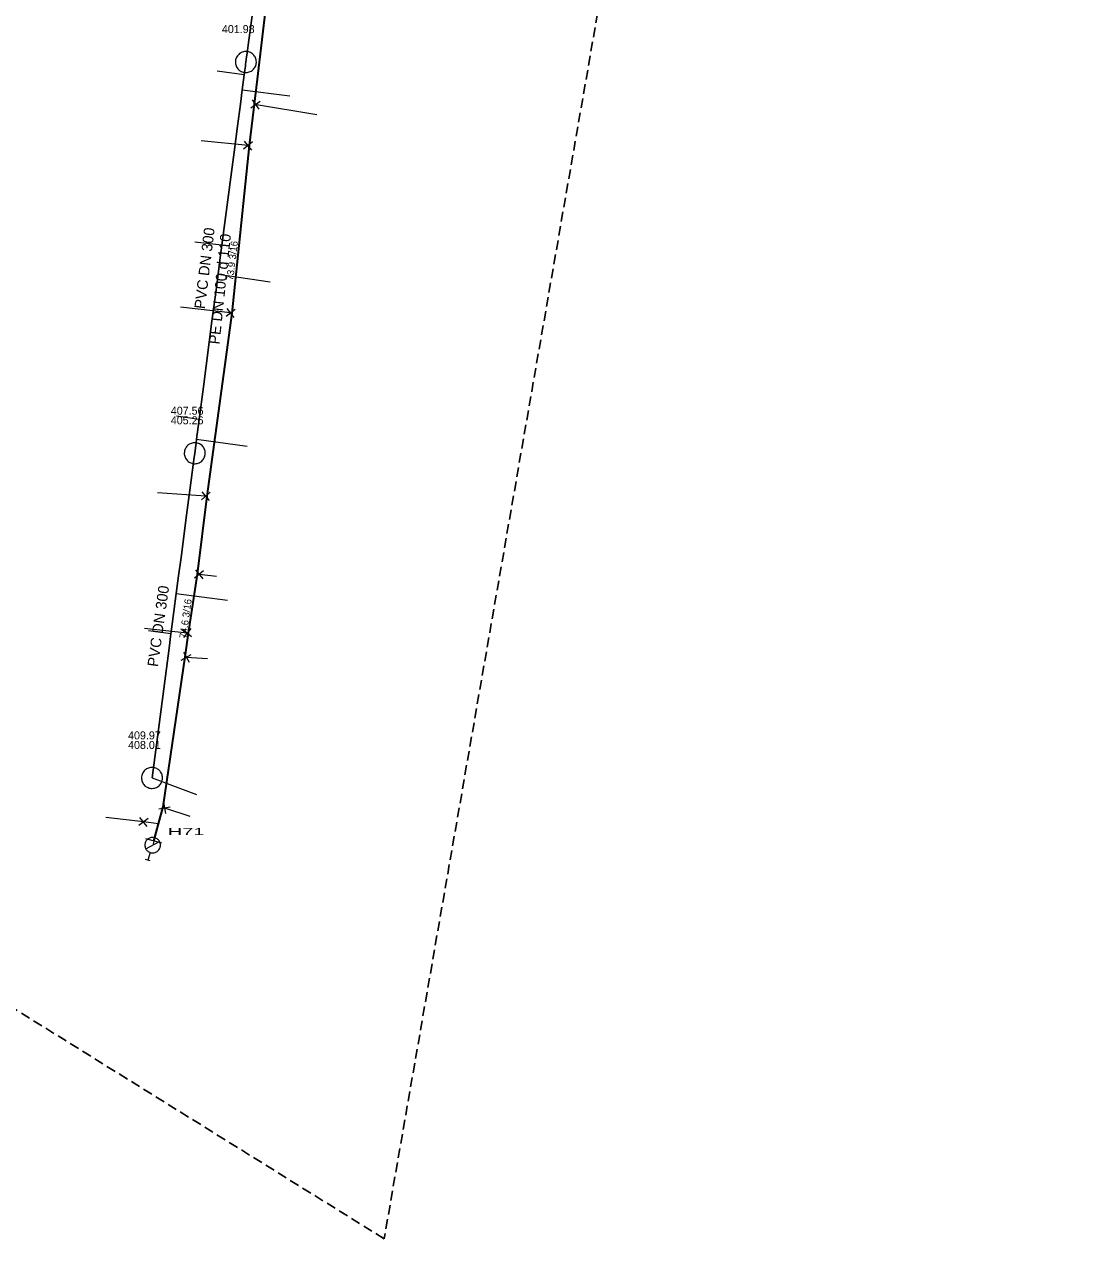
# Model space of a CAD drawing. Extents: x -772952 to -772403, y -1033777 to -1033210.
# Drawn here: x -772682 to -772562.5, y -1033777 to -1033640.4 of the extents above; entities that cross this region are included whole.
import ezdxf

# ---------------------------------------------------------------- set-up
doc = ezdxf.new("R2010")
doc.units = 0
doc.header["$LTSCALE"] = 0.36
doc.linetypes.add('MEDIUM_DASHED', pattern=[4.5, 3, -1.5])
for name, color, linetype, lineweight in [('15', 7, 'Continuous', 13), ('16', 7, 'Continuous', 35), ('2', 7, 'Continuous', 25), ('20', 7, 'Continuous', 13), ('4', 7, 'Continuous', 13), ('57', 7, 'Continuous', 13), ('59', 7, 'Continuous', 13), ('62', 7, 'MEDIUM_DASHED', 25)]:
    doc.layers.add(name, color=color, linetype=linetype, lineweight=lineweight)
for name, color, linetype in [('17', 7, 'Continuous'), ('3', 7, 'Continuous'), ('6', 7, 'Continuous')]:
    doc.layers.add(name, color=color, linetype=linetype)

msp = doc.modelspace()

# ---------------------------------------------------------------- linework, layer by layer
at = {"layer": '15'}
for p, q in [((-772656.539, -1033649.771), (-772655.481, -1033649.013)), ((-772656.386, -1033648.869), (-772655.637, -1033649.919)), ((-772656.328, -1033653.611), (-772657.337, -1033654.434)), ((-772656.425, -1033654.521), (-772657.238, -1033653.519)), ((-772658.292, -1033672.446), (-772659.311, -1033673.257)), ((-772658.4, -1033673.355), (-772659.201, -1033672.343)), ((-772661.088, -1033693.018), (-772662.07, -1033693.873)), ((-772661.155, -1033693.931), (-772662, -1033692.955)), ((-772662.851, -1033702.643), (-772661.838, -1033701.826)), ((-772662.749, -1033701.734), (-772661.941, -1033702.74)), ((-772663.19, -1033709.263), (-772664.194, -1033708.453)), ((-772663.285, -1033708.353), (-772664.1, -1033709.368)), ((-772664.357, -1033711.891), (-772663.221, -1033711.255)), ((-772664.104, -1033711.011), (-772663.477, -1033712.139)), ((-772666.362, -1033727.866), (-772666.142, -1033729.138)), ((-772666.891, -1033728.613), (-772665.609, -1033728.388)), ((-772668.088, -1033729.702), (-772669.113, -1033730.505)), ((-772668.203, -1033730.61), (-772668.997, -1033729.592)), ((-772666.521, -1033732.499), (-772668.319, -1033732.018))]:
    msp.add_line(p, q, dxfattribs=at)
at = {"layer": '16'}
msp.add_lwpolyline([(-772667.42, -1033732.259), (-772666.897, -1033730.304), (-772666.388, -1033728.405), (-772663.901, -1033711.543), (-772663.543, -1033708.874), (-772662.528, -1033702.243), (-772661.418, -1033693.445), (-772658.618, -1033672.89), (-772656.675, -1033654.019), (-772655.778, -1033646.539), (-772654.291, -1033634.155), (-772653.179, -1033627.482), (-772651.945, -1033620.636), (-772651.409, -1033616.616), (-772649.087, -1033602.85)], dxfattribs=at)
at = {"layer": '2'}
for points in [[(-772651.56, -1033604.63), (-772651.679, -1033605.495), (-772651.717, -1033605.774), (-772651.903, -1033607.115), (-772652.079, -1033608.397), (-772652.268, -1033609.761), (-772652.464, -1033611.185), (-772652.49, -1033611.37), (-772652.856, -1033614.025), (-772653.255, -1033616.91), (-772653.475, -1033618.506), (-772653.848, -1033621.205), (-772654.258, -1033624.176), (-772654.637, -1033626.924), (-772655.581, -1033633.763), (-772655.924, -1033636.247), (-772656.043, -1033637.113), (-772656.435, -1033639.951), (-772656.816, -1033642.712), (-772656.941, -1033643.616), (-772656.999, -1033644.037), (-772657.08, -1033644.62)], [(-772657.08, -1033644.62), (-772657.113, -1033644.875), (-772657.139, -1033645.074), (-772657.197, -1033645.521), (-772657.266, -1033646.046), (-772657.49, -1033647.763), (-772657.7, -1033649.365), (-772658.023, -1033651.837), (-772658.407, -1033654.776), (-772658.775, -1033657.585), (-772659.034, -1033659.567), (-772659.774, -1033665.23), (-772659.995, -1033666.923), (-772660.202, -1033668.502), (-772660.356, -1033669.684), (-772660.68, -1033672.157), (-772660.893, -1033673.789), (-772661.858, -1033681.165), (-772662.33, -1033684.83), (-772662.628, -1033687.058), (-772662.685, -1033687.498), (-772662.722, -1033687.775), (-772662.83, -1033688.626)], [(-772662.83, -1033688.626), (-772662.924, -1033689.318), (-772662.964, -1033689.619), (-772663.233, -1033691.667), (-772663.528, -1033693.904), (-772663.823, -1033696.15), (-772664.104, -1033698.283), (-772664.375, -1033700.343), (-772664.649, -1033702.427), (-772664.908, -1033704.397), (-772665.175, -1033706.42), (-772665.439, -1033708.43), (-772665.506, -1033708.938), (-772665.704, -1033710.551), (-772667.64, -1033725.15)]]:
    msp.add_lwpolyline(points, dxfattribs=at)
at = {"layer": '20'}
for p, q in [((-772668.34, -1033733.113), (-772666.782, -1033732.314)), ((-772667.847, -1033734.481), (-772668.362, -1033734.315)), ((-772667.833, -1033733.557), (-772668.104, -1033734.398))]:
    msp.add_line(p, q, dxfattribs=at)
msp.add_lwpolyline([(-772668.398, -1033732.445), (-772668.422, -1033732.532), (-772668.437, -1033732.622), (-772668.441, -1033732.715), (-772668.437, -1033732.804), (-772668.422, -1033732.895), (-772668.398, -1033732.985), (-772668.365, -1033733.069), (-772668.324, -1033733.152), (-772668.273, -1033733.227), (-772668.216, -1033733.298), (-772668.15, -1033733.363), (-772668.079, -1033733.422), (-772668.003, -1033733.472), (-772667.921, -1033733.513), (-772667.835, -1033733.545), (-772667.746, -1033733.569), (-772667.656, -1033733.584), (-772667.565, -1033733.588), (-772667.473, -1033733.582), (-772667.382, -1033733.567), (-772667.294, -1033733.543), (-772667.208, -1033733.511), (-772667.127, -1033733.468), (-772667.051, -1033733.42), (-772666.979, -1033733.361), (-772666.914, -1033733.295), (-772666.858, -1033733.225), (-772666.807, -1033733.147), (-772666.766, -1033733.066), (-772666.732, -1033732.98), (-772666.71, -1033732.892), (-772666.696, -1033732.803), (-772666.691, -1033732.71), (-772666.696, -1033732.62), (-772666.711, -1033732.529), (-772666.734, -1033732.439), (-772666.768, -1033732.355), (-772666.809, -1033732.272), (-772666.86, -1033732.197), (-772666.917, -1033732.126), (-772666.982, -1033732.061), (-772667.054, -1033732.002), (-772667.131, -1033731.954), (-772667.211, -1033731.911), (-772667.298, -1033731.879), (-772667.387, -1033731.855), (-772667.477, -1033731.842), (-772667.568, -1033731.836), (-772667.66, -1033731.842), (-772667.751, -1033731.857), (-772667.838, -1033731.881), (-772667.924, -1033731.913), (-772668.005, -1033731.956), (-772668.082, -1033732.005), (-772668.154, -1033732.063), (-772668.219, -1033732.129), (-772668.275, -1033732.199), (-772668.325, -1033732.277), (-772668.366, -1033732.358), (-772668.398, -1033732.443)], dxfattribs=at)
at = {"layer": '4'}
for points in [[(-772655.899, -1033644.62), (-772655.905, -1033644.501), (-772655.923, -1033644.384), (-772655.952, -1033644.268), (-772655.993, -1033644.157), (-772656.045, -1033644.05), (-772656.108, -1033643.949), (-772656.181, -1033643.854), (-772656.262, -1033643.768), (-772656.352, -1033643.69), (-772656.45, -1033643.621), (-772656.553, -1033643.563), (-772656.662, -1033643.516), (-772656.776, -1033643.479), (-772656.892, -1033643.454), (-772657.01, -1033643.442), (-772657.129, -1033643.441), (-772657.248, -1033643.452), (-772657.364, -1033643.475), (-772657.478, -1033643.509), (-772657.588, -1033643.555), (-772657.693, -1033643.612), (-772657.791, -1033643.679), (-772657.882, -1033643.755), (-772657.965, -1033643.84), (-772658.039, -1033643.934), (-772658.103, -1033644.034), (-772658.157, -1033644.14), (-772658.2, -1033644.251), (-772658.232, -1033644.365), (-772658.251, -1033644.483), (-772658.259, -1033644.602), (-772658.255, -1033644.72), (-772658.239, -1033644.838), (-772658.211, -1033644.954), (-772658.172, -1033645.066), (-772658.121, -1033645.174), (-772658.06, -1033645.276), (-772657.989, -1033645.372), (-772657.909, -1033645.459), (-772657.82, -1033645.539), (-772657.724, -1033645.609), (-772657.621, -1033645.669), (-772657.513, -1033645.718), (-772657.4, -1033645.756), (-772657.284, -1033645.782), (-772657.166, -1033645.797), (-772657.047, -1033645.8), (-772656.929, -1033645.791), (-772656.811, -1033645.77), (-772656.697, -1033645.737), (-772656.587, -1033645.693), (-772656.481, -1033645.638), (-772656.382, -1033645.572), (-772656.289, -1033645.497), (-772656.205, -1033645.413), (-772656.13, -1033645.321), (-772656.064, -1033645.222), (-772656.008, -1033645.117), (-772655.964, -1033645.007), (-772655.93, -1033644.893), (-772655.909, -1033644.776), (-772655.899, -1033644.657)], [(-772661.649, -1033688.626), (-772661.656, -1033688.507), (-772661.674, -1033688.39), (-772661.703, -1033688.274), (-772661.744, -1033688.163), (-772661.796, -1033688.056), (-772661.858, -1033687.955), (-772661.931, -1033687.86), (-772662.012, -1033687.774), (-772662.103, -1033687.696), (-772662.201, -1033687.627), (-772662.304, -1033687.569), (-772662.413, -1033687.522), (-772662.527, -1033687.485), (-772662.642, -1033687.46), (-772662.761, -1033687.448), (-772662.88, -1033687.447), (-772662.999, -1033687.458), (-772663.115, -1033687.481), (-772663.228, -1033687.515), (-772663.338, -1033687.561), (-772663.443, -1033687.618), (-772663.542, -1033687.685), (-772663.632, -1033687.761), (-772663.716, -1033687.846), (-772663.789, -1033687.94), (-772663.853, -1033688.04), (-772663.907, -1033688.146), (-772663.951, -1033688.257), (-772663.983, -1033688.371), (-772664.002, -1033688.489), (-772664.01, -1033688.608), (-772664.005, -1033688.726), (-772663.99, -1033688.844), (-772663.962, -1033688.96), (-772663.923, -1033689.072), (-772663.872, -1033689.18), (-772663.811, -1033689.282), (-772663.74, -1033689.378), (-772663.659, -1033689.465), (-772663.571, -1033689.545), (-772663.475, -1033689.615), (-772663.372, -1033689.675), (-772663.264, -1033689.724), (-772663.151, -1033689.762), (-772663.034, -1033689.788), (-772662.917, -1033689.803), (-772662.798, -1033689.806), (-772662.679, -1033689.797), (-772662.561, -1033689.776), (-772662.448, -1033689.743), (-772662.338, -1033689.699), (-772662.232, -1033689.644), (-772662.132, -1033689.578), (-772662.039, -1033689.503), (-772661.956, -1033689.419), (-772661.88, -1033689.327), (-772661.815, -1033689.228), (-772661.759, -1033689.123), (-772661.715, -1033689.013), (-772661.681, -1033688.899), (-772661.659, -1033688.782), (-772661.649, -1033688.663)], [(-772666.46, -1033725.15), (-772666.466, -1033725.031), (-772666.484, -1033724.914), (-772666.513, -1033724.798), (-772666.554, -1033724.687), (-772666.606, -1033724.58), (-772666.669, -1033724.479), (-772666.742, -1033724.384), (-772666.823, -1033724.298), (-772666.913, -1033724.22), (-772667.011, -1033724.151), (-772667.114, -1033724.093), (-772667.223, -1033724.046), (-772667.337, -1033724.009), (-772667.453, -1033723.984), (-772667.571, -1033723.972), (-772667.69, -1033723.971), (-772667.809, -1033723.982), (-772667.925, -1033724.005), (-772668.039, -1033724.039), (-772668.149, -1033724.085), (-772668.254, -1033724.142), (-772668.352, -1033724.209), (-772668.443, -1033724.285), (-772668.526, -1033724.37), (-772668.6, -1033724.464), (-772668.664, -1033724.564), (-772668.718, -1033724.67), (-772668.761, -1033724.781), (-772668.793, -1033724.895), (-772668.812, -1033725.013), (-772668.82, -1033725.132), (-772668.816, -1033725.25), (-772668.8, -1033725.368), (-772668.772, -1033725.484), (-772668.733, -1033725.596), (-772668.682, -1033725.704), (-772668.621, -1033725.806), (-772668.55, -1033725.902), (-772668.47, -1033725.989), (-772668.381, -1033726.069), (-772668.285, -1033726.139), (-772668.182, -1033726.199), (-772668.074, -1033726.248), (-772667.961, -1033726.286), (-772667.845, -1033726.312), (-772667.727, -1033726.327), (-772667.608, -1033726.33), (-772667.49, -1033726.321), (-772667.372, -1033726.3), (-772667.258, -1033726.267), (-772667.148, -1033726.223), (-772667.042, -1033726.168), (-772666.943, -1033726.102), (-772666.85, -1033726.027), (-772666.766, -1033725.943), (-772666.691, -1033725.851), (-772666.625, -1033725.752), (-772666.569, -1033725.647), (-772666.525, -1033725.537), (-772666.491, -1033725.423), (-772666.47, -1033725.306), (-772666.46, -1033725.187)]]:
    msp.add_lwpolyline(points, close=True, dxfattribs=at)
at = {"layer": '57'}
for p, q in [((-772657.266, -1033646.046), (-772660.31, -1033645.64)), ((-772657.49, -1033647.763), (-772652.15, -1033648.43)), ((-772659.774, -1033665.23), (-772662.82, -1033664.87)), ((-772660.202, -1033668.502), (-772654.35, -1033669.36)), ((-772662.33, -1033684.83), (-772664.87, -1033684.47)), ((-772662.628, -1033687.058), (-772656.92, -1033687.84)), ((-772664.908, -1033704.397), (-772659.13, -1033705.16)), ((-772665.506, -1033708.938), (-772668.03, -1033708.59))]:
    msp.add_line(p, q, dxfattribs=at)
msp.add_lwpolyline([(-772667.64, -1033725.15), (-772664.722, -1033726.24), (-772662.648, -1033727.016)], dxfattribs=at)
at = {"layer": '59'}
for p, q in [((-772656.118, -1033649.375), (-772649.089, -1033650.533)), ((-772667.42, -1033732.259), (-772667.567, -1033732.713))]:
    msp.add_line(p, q, dxfattribs=at)
for points in [[(-772656.676, -1033654.023), (-772656.832, -1033654.022), (-772662.129, -1033653.484)], [(-772658.619, -1033672.891), (-772658.801, -1033672.851), (-772664.437, -1033672.213)], [(-772661.413, -1033693.44), (-772661.578, -1033693.445), (-772667.029, -1033693.07)], [(-772662.529, -1033702.244), (-772662.346, -1033702.236), (-772660.391, -1033702.445)], [(-772663.538, -1033708.843), (-772663.692, -1033708.86), (-772668.475, -1033708.36)], [(-772663.901, -1033711.543), (-772663.791, -1033711.574), (-772661.388, -1033711.718)], [(-772666.389, -1033728.405), (-772666.252, -1033728.501), (-772663.391, -1033729.448)], [(-772666.897, -1033730.304), (-772668.6, -1033730.103), (-772672.824, -1033729.595)]]:
    msp.add_lwpolyline(points, dxfattribs=at)
at = {"layer": '62'}
msp.add_lwpolyline([(-772641.514, -1033776.98), (-772641.529, -1033776.987), (-772951.708, -1033584.106), (-772846.395, -1033249.938), (-772562.451, -1033323.146)], close=True, dxfattribs=at)

# ---------------------------------------------------------------- texts
at = {"layer": '17'}
msp.add_text('PE DN 100 d 110 ', height=1.2, rotation=84, dxfattribs=at).set_placement((-772660.051, -1033676.424))
at = {"layer": '20', "width": 2.1}
msp.add_text('H71 ', height=0.8, dxfattribs=at).set_placement((-772665.866, -1033731.59))
at = {"layer": '3'}
for s, height, rotation, p in [('PVC DN 300', 1.2, 83, (-772661.696, -1033672.447)), ('73.9 3/16', 0.8, 83, (-772658.504, -1033669.231)), ('PVC DN 300', 1.2, 82, (-772666.983, -1033712.709)), ('74.6 3/16', 0.8, 82, (-772663.786, -1033709.497))]:
    msp.add_text(s, height=height, rotation=rotation, dxfattribs=at).set_placement(p)
at = {"layer": '6'}
for s, p in [('401.98', (-772659.778, -1033641.364)), ('407.56', (-772665.528, -1033684.294)), ('405.26', (-772665.528, -1033685.371)), ('409.97', (-772670.338, -1033720.817)), ('408.01', (-772670.338, -1033721.894))]:
    msp.add_text(s, height=0.9, dxfattribs=at).set_placement(p)

doc.saveas('drawing.dxf')
